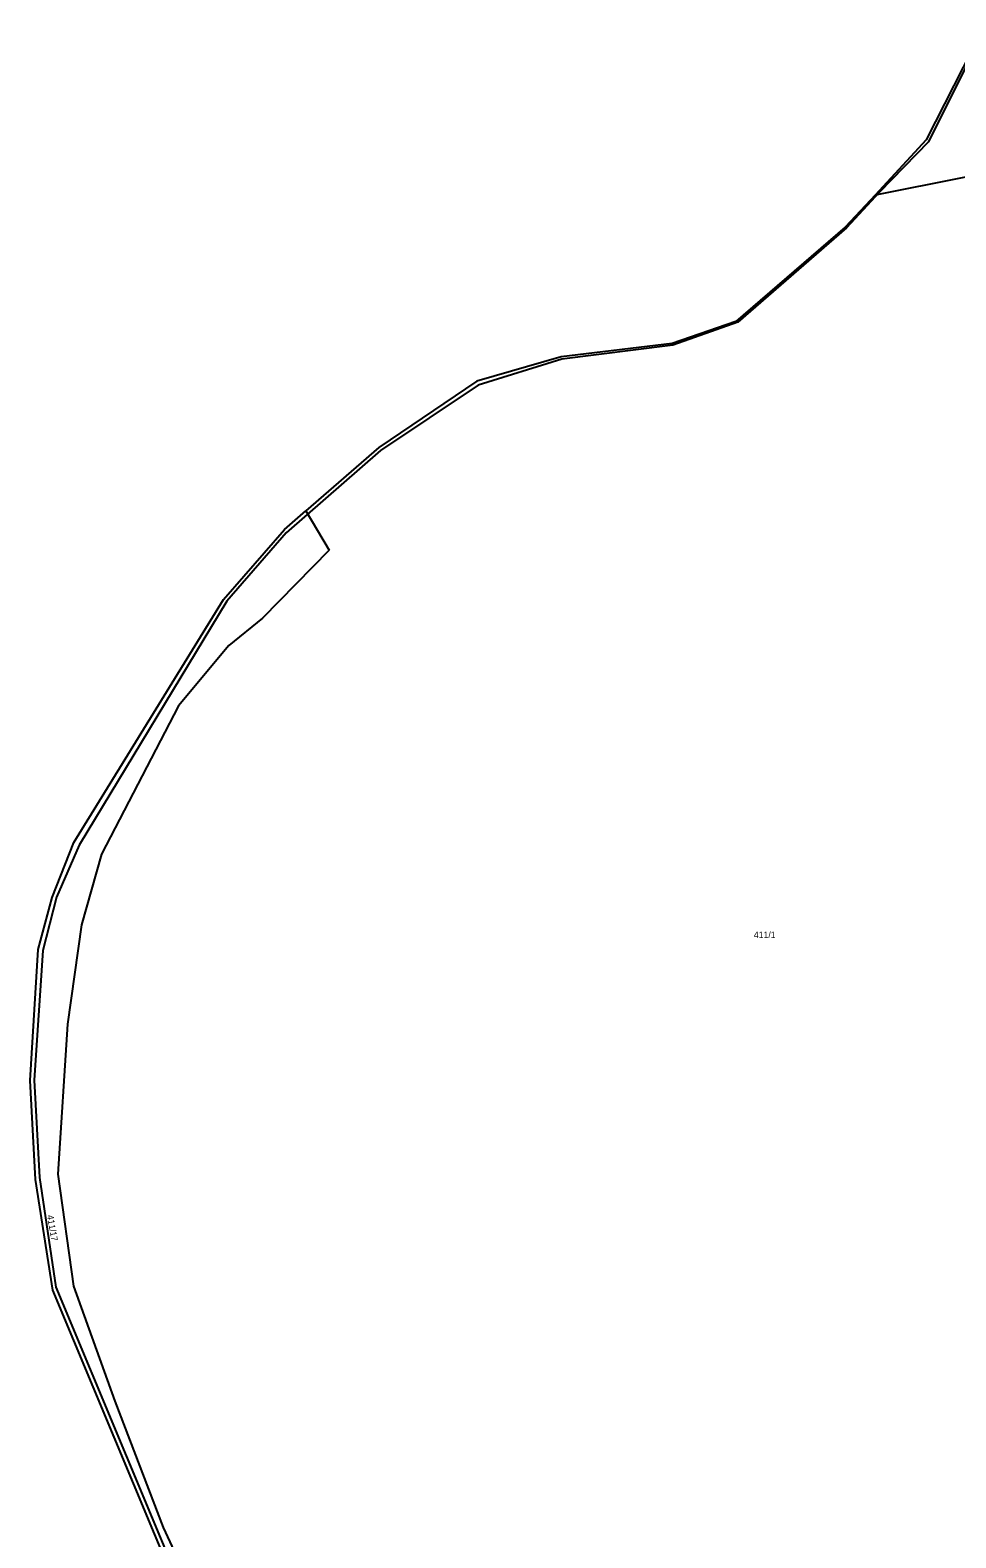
# Model space of a CAD drawing. Extents: x -880531 to -877616, y -1023932 to -1021350.
# Drawn here: x -880530.7 to -880287.7, y -1022219 to -1021822.9 of the extents above; entities that cross this region are included whole.
import ezdxf

# ---------------------------------------------------------------- set-up
doc = ezdxf.new("R2010")
doc.units = 0
for name, color, linetype in [('Hranice parcel', 7, 'Continuous'), ('Parcelní čísla', 7, 'Continuous'), ('Vnitřní kresba', 7, 'Continuous')]:
    doc.layers.add(name, color=color, linetype=linetype)

msp = doc.modelspace()

# ---------------------------------------------------------------- linework, layer by layer
at = {"layer": 'Hranice parcel'}
msp.add_line((-880458.37, -1021949.23), (-880452.22, -1021959.53), dxfattribs=at)
for points in [[(-880280.95, -1021823.18), (-880295.5, -1021851.75), (-880308.92, -1021866.24)], [(-880256.94, -1021858.64), (-880285.61, -1021861.6), (-880308.92, -1021866.24)], [(-880308.92, -1021866.24), (-880316.75, -1021874.64), (-880345.49, -1021899.44), (-880362.19, -1021905.21), (-880391.36, -1021908.72), (-880413.46, -1021915.14), (-880439.14, -1021932.52), (-880458.37, -1021949.23)], [(-880438.9, -1022312.23), (-880448.03, -1022299.45), (-880455.75, -1022284.78), (-880487.48, -1022243.34), (-880524.79, -1022153.92), (-880529.34, -1022124.84), (-880530.7, -1022098.83), (-880528.56, -1022064.4), (-880524.89, -1022050.76), (-880519.28, -1022036.32), (-880479.95, -1021972.5), (-880463.94, -1021954.07), (-880458.37, -1021949.23)], [(-880452.22, -1021959.53), (-880469.68, -1021977.36), (-880478.53, -1021984.54), (-880491.76, -1022000.43), (-880511.96, -1022039.42), (-880517.25, -1022057.99), (-880520.93, -1022084.07), (-880523.46, -1022123.46), (-880519.31, -1022152.85), (-880508.5, -1022183.09), (-880495.79, -1022216.24), (-880482.58, -1022244.73), (-880452.91, -1022281.59), (-880435.85, -1022300.63), (-880429.09, -1022312.44), (-880420.6, -1022319.4), (-880402.34, -1022335.61), (-880374.63, -1022361.05), (-880347.08, -1022391.39)]]:
    msp.add_lwpolyline(points, dxfattribs=at)
at = {"layer": 'Vnitřní kresba'}
for points in [[(-880280.32, -1021822.93), (-880294.9, -1021852.25), (-880307.77, -1021865.47), (-880316.44, -1021874.89), (-880344.91, -1021899.64), (-880361.99, -1021905.7), (-880391.18, -1021909.4), (-880413.12, -1021916.16), (-880438.71, -1021933.34), (-880463.52, -1021954.98), (-880479.1, -1021972.95), (-880517.86, -1022036.99)], [(-880517.86, -1022036.99), (-880523.75, -1022050.69), (-880527.41, -1022064.69), (-880529.64, -1022098.73), (-880528.21, -1022124.34), (-880523.98, -1022153.1), (-880487.02, -1022241.79), (-880455.17, -1022282.98), (-880446.92, -1022298.93), (-880437.86, -1022312.14), (-880391.59, -1022357.95)]]:
    msp.add_lwpolyline(points, dxfattribs=at)

# ---------------------------------------------------------------- texts
at = {"layer": 'Parcelní čísla'}
msp.add_text('411/1', height=1.7, dxfattribs=at).set_placement((-880340.73, -1022061.42))
msp.add_text('411/17', height=1.7, rotation=280, dxfattribs=at).set_placement((-880526.306, -1022134.309))

doc.saveas('drawing.dxf')
